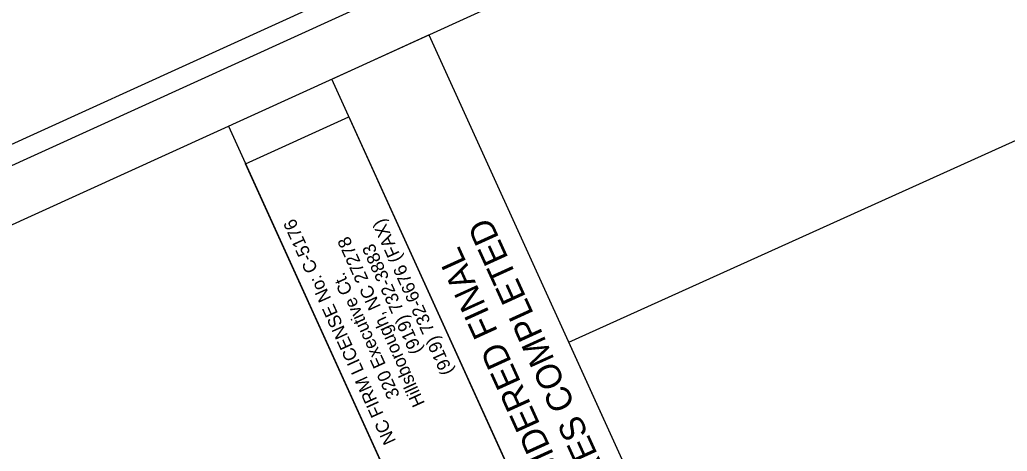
# Model space of a CAD drawing. Extents: x 2097307 to 2099001, y 683921 to 685907.
# Drawn here: x 2097458.2 to 2097686.2, y 685450.9 to 685550.5 of the extents above; entities that cross this region are included whole.
import ezdxf

# ---------------------------------------------------------------- set-up
doc = ezdxf.new("R2010")
doc.units = 0
for name, color, linetype in [('Sheet Block Title CELL', 7, 'Continuous'), ('Sheet Layout Plan Border', 7, 'Continuous'), ('Sheet Plan CELL', 7, 'Continuous'), ('Sheet Plot Border Inside CELL', 7, 'Continuous'), ('Sheet Plot Border Outside CELL', 7, 'Continuous'), ('Sheet Sticker Exception Certification CELL', 7, 'Continuous'), ('Sheet Title CELL', 7, 'Continuous')]:
    doc.layers.add(name, color=color, linetype=linetype)

msp = doc.modelspace()

# ---------------------------------------------------------------- linework, layer by layer
at = {"layer": 'Sheet Block Title CELL'}
msp.add_lwpolyline([(2097593.2, 685335.14), (2097510.34, 685517.23), (2097534.24, 685528.11), (2097617.1, 685346.01)], close=True, dxfattribs=at)
at = {"layer": 'Sheet Layout Plan Border'}
msp.add_lwpolyline([(2098458.66, 685511.51), (2098911.14, 684517.12), (2097955.44, 684082.23), (2097420.98, 685256.77), (2097639.51, 685356.21), (2097584.97, 685476.06), (2098243.4, 685773.28), (2098379.01, 685475.27)], close=True, dxfattribs=at)
at = {"layer": 'Sheet Plan CELL'}
msp.add_line((2098289.88, 685882.41), (2097334.17, 685447.53), dxfattribs=at)
at = {"layer": 'Sheet Plot Border Inside CELL'}
msp.add_lwpolyline([(2098977, 684378.44), (2098287, 685894.78), (2097326.75, 685457.84), (2098016.75, 683941.49)], close=True, dxfattribs=at)
at = {"layer": 'Sheet Plot Border Outside CELL'}
msp.add_lwpolyline([(2099000.59, 684374.9), (2098303.35, 685907.17), (2097306.68, 685453.65), (2098003.93, 683921.37)], close=True, dxfattribs=at)
at = {"layer": 'Sheet Sticker Exception Certification CELL'}
for p, q in [((2097530.31, 685536.78), (2097552.72, 685546.97)), ((2097552.71, 685546.97), (2097639.51, 685356.21)), ((2097617.1, 685346.01), (2097530.3, 685536.77))]:
    msp.add_line(p, q, dxfattribs=at)
at = {"layer": 'Sheet Title CELL'}
msp.add_line((2097506.4, 685525.9), (2097593.2, 685335.14), dxfattribs=at)

# ---------------------------------------------------------------- texts
at = {"layer": 'Sheet Block Title CELL'}
for s, p in [('NC FIRM LICENSE No: C-5176', (2097545.16, 685453.26)), ('(919) 732-6676 (FAX)', (2097558.4, 685469.28)), ('Hillsborough, NC 27278', (2097551.84, 685461.96)), ('(919) 732-3883', (2097551.26, 685474.1)), ('320 Executive Ct.', (2097546.05, 685463.81))]:
    msp.add_text(s, height=3.0009, rotation=114.4674, dxfattribs=at).set_placement(p)
at = {"layer": 'Sheet Sticker Exception Certification CELL'}
for s, p in [('UNLESS ALL SIGNATURES COMPLETED', (2097628.41, 685369.58)), ('DOCUMENT NOT CONSIDERED FINAL', (2097617.82, 685370.6))]:
    msp.add_text(s, height=5.7623, rotation=114.4674, dxfattribs=at).set_placement(p)

doc.saveas('drawing.dxf')
